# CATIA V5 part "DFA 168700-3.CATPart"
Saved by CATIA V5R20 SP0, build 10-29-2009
Part number: DFA 168700-3
Revision: ANY
Definition: UNKNOWN
Nomenclature: DFA 168700-3
Source: Unknown
Bounding box of the stored display mesh (mm): x -3 to 3, y 0 to 4.95, z -3.464 to 3.464
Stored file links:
  C:\Users\Utente\Desktop\IO LAVORO\3D X SITO CF\CUMSA\3D files FA\FA 168712-21\DFA 168700-3.CATPart
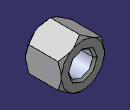
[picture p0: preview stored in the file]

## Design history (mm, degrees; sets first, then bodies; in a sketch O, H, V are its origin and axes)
Body1 "Cortar-Extruir3" (main body)
  Solid1: solid without history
